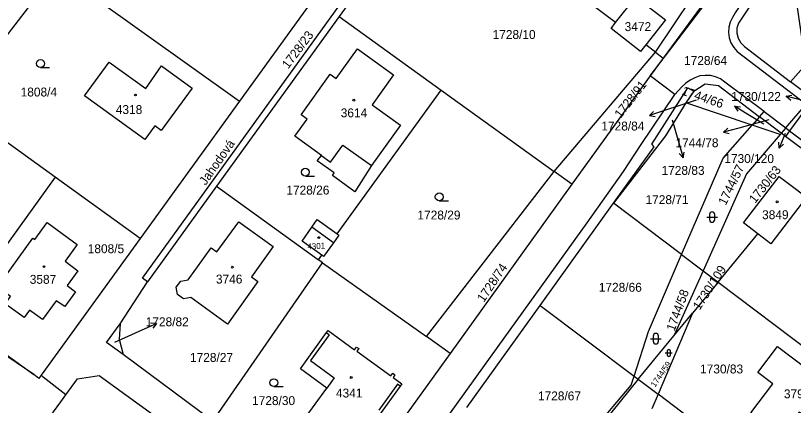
# Model space of a CAD drawing. Extents: x -679220 to -673243, y -1075091 to -1066557.
# Drawn here: x -677162.5 to -677014, y -1072302.1 to -1072227.6 of the extents above; entities that cross this region are included whole.
import ezdxf

# ---------------------------------------------------------------- set-up
doc = ezdxf.new("R2010")
doc.units = 0
for name, color, linetype in [('Hranice parcel', 7, 'Continuous'), ('Parcelní čísla', 7, 'Continuous'), ('Pop  PČ popisy', 7, 'Continuous'), ('Vnitřní kresba', 7, 'Continuous'), ('Značky budov', 7, 'Continuous'), ('Značky kultur', 7, 'Continuous')]:
    doc.layers.add(name, color=color, linetype=linetype)

msp = doc.modelspace()

# ---------------------------------------------------------------- linework, layer by layer
at = {"layer": 'Hranice parcel'}
for p, q in [((-677097.67, -1072213.39), (-677119.75, -1072243.96)), ((-677040.31, -1072234.56), (-677027.35, -1072215.28)), ((-677174.28, -1072244.49), (-677154.6, -1072218.99)), ((-677154.6, -1072218.99), (-677119.75, -1072243.96)), ((-677047.9, -1072228.9), (-677062.31, -1072218.1)), ((-677100.67, -1072227.78), (-677124.1, -1072260.21)), ((-677100.67, -1072227.78), (-677081.22, -1072241.84)), ((-677040.31, -1072234.56), (-677042.16, -1072233.17)), ((-677059.66, -1072257.41), (-677040.31, -1072234.56)), ((-677038.82, -1072235.71), (-677041.29, -1072239.09)), ((-677040.31, -1072234.56), (-677038.82, -1072235.71)), ((-677041.29, -1072239.09), (-677056.26, -1072259.8)), ((-677010.47, -1072243.28), (-677014.49, -1072240.22)), ((-677028.28, -1072240.94), (-677020.41, -1072246.91)), ((-677101.06, -1072269.31), (-677081.22, -1072241.84)), ((-677081.22, -1072241.84), (-677059.66, -1072257.41)), ((-677032.98, -1072242.04), (-677034.52, -1072244.26)), ((-677154.92, -1072258.47), (-677174.28, -1072244.49)), ((-677119.75, -1072243.96), (-677138.7, -1072270.17)), ((-677021.83, -1072248.52), (-677034.52, -1072244.26)), ((-677015.41, -1072249.05), (-677011.5, -1072244.49)), ((-677020.41, -1072246.91), (-677019.54, -1072245.93)), ((-677019.54, -1072245.93), (-677015.41, -1072249.05)), ((-677011.13, -1072244.77), (-677014.68, -1072249.6)), ((-677020.41, -1072246.91), (-677021.83, -1072248.52)), ((-677016.27, -1072250.05), (-677020.41, -1072246.91)), ((-677016.49, -1072250.31), (-677021.83, -1072248.52)), ((-677015.41, -1072249.05), (-677016.27, -1072250.05)), ((-677015.41, -1072249.05), (-677014.68, -1072249.6)), ((-677016.27, -1072250.05), (-677016.49, -1072250.31)), ((-677015.46, -1072250.66), (-677016.27, -1072250.05)), ((-677014.68, -1072249.6), (-677015.46, -1072250.66)), ((-677009.25, -1072255.35), (-677015.46, -1072250.66)), ((-677084.04, -1072288.92), (-677059.66, -1072257.41)), ((-677056.26, -1072259.8), (-677059.66, -1072257.41)), ((-677138.7, -1072270.17), (-677154.92, -1072258.47)), ((-677124.1, -1072260.21), (-677137.29, -1072278.46)), ((-677124.1, -1072260.21), (-677104.64, -1072274.26)), ((-677056.26, -1072259.8), (-677079.53, -1072292.18)), ((-677062.3, -1072282.96), (-677048.3, -1072263.46)), ((-677035.31, -1072273.26), (-677048.3, -1072263.46)), ((-677104.88, -1072266.54), (-677101.06, -1072269.31)), ((-677101.06, -1072269.31), (-677100.73, -1072269.55)), ((-677028.33, -1072278.52), (-677020.74, -1072269.31)), ((-677138.7, -1072270.17), (-677157.58, -1072296.32)), ((-677104.02, -1072273.4), (-677107.79, -1072270.69)), ((-677159.03, -1072296.2), (-677193.06, -1072273.1)), ((-677104.64, -1072274.26), (-677104.02, -1072273.4)), ((-677103.85, -1072274.86), (-677104.64, -1072274.26)), ((-677103.68, -1072273.65), (-677104.02, -1072273.4)), ((-677035.31, -1072273.26), (-677031.21, -1072276.35)), ((-677124.82, -1072305.07), (-677103.85, -1072274.86)), ((-677103.85, -1072274.86), (-677084.04, -1072288.92)), ((-677031.21, -1072276.35), (-677036.76, -1072288.76)), ((-677031.21, -1072276.35), (-677028.33, -1072278.52)), ((-677142.52, -1072286.49), (-677137.29, -1072278.46)), ((-677028.33, -1072278.52), (-677033.21, -1072284.45)), ((-677028.33, -1072278.52), (-676999.23, -1072300.52)), ((-677076.29, -1072302.46), (-677062.3, -1072282.96)), ((-677062.3, -1072282.96), (-677044.39, -1072296.48)), ((-677033.21, -1072284.45), (-677039.8, -1072299.95)), ((-677036.76, -1072288.76), (-677033.21, -1072284.45)), ((-677079.53, -1072292.18), (-677084.04, -1072288.92)), ((-677043.6, -1072297.08), (-677036.76, -1072288.76)), ((-677124.82, -1072305.07), (-677141.95, -1072292.37)), ((-677044.39, -1072296.48), (-677043.6, -1072297.08)), ((-677043.6, -1072297.08), (-677058.73, -1072315.73)), ((-677043.6, -1072297.08), (-677039.8, -1072299.95)), ((-677039.8, -1072299.95), (-677040.98, -1072302.71)), ((-677013.7, -1072319.67), (-677039.8, -1072299.95))]:
    msp.add_line(p, q, dxfattribs=at)
for points in [[(-677137.29, -1072278.46), (-677138.25, -1072277.77), (-677074.28, -1072189.03), (-677070.45, -1072187.06)], [(-677070.45, -1072187.06), (-677078.7, -1072197.36), (-677100.67, -1072227.78)], [(-677041.29, -1072239.09), (-677020.3, -1072211.54), (-677004.4, -1072187.4)], [(-677000.68, -1072190.31), (-677010.81, -1072205.46), (-677025.05, -1072227.04), (-677025.58, -1072227.92), (-677026.06, -1072228.81), (-677026.31, -1072229.79), (-677026.34, -1072230.8), (-677026.21, -1072231.82), (-677025.88, -1072232.78), (-677025.36, -1072233.67), (-677024.7, -1072234.47), (-677011.5, -1072244.49)], [(-677000.98, -1072193.99), (-677009.55, -1072206.46), (-677019.04, -1072220.85), (-677024.42, -1072229.04), (-677024.78, -1072230), (-677024.76, -1072230.97), (-677024.5, -1072231.92), (-677024.01, -1072232.8), (-677023.32, -1072233.51), (-677014.49, -1072240.22)], [(-677014.49, -1072240.22), (-677011.6, -1072236.95), (-677013.33, -1072225.14), (-676993.8, -1072200.73)], [(-677026.98, -1072214.73), (-677026.28, -1072215.76), (-677026.13, -1072216.83), (-677026.28, -1072217.83), (-677026.67, -1072218.76), (-677027.15, -1072219.65), (-677027.69, -1072220.49), (-677038.82, -1072235.71)], [(-677047.9, -1072228.9), (-677044.06, -1072224.02), (-677038.38, -1072228.38), (-677042.16, -1072233.17)], [(-677042.16, -1072233.17), (-677043.16, -1072234.45), (-677048.78, -1072230.02), (-677047.9, -1072228.9)], [(-677104.87, -1072255.34), (-677104.07, -1072254.32), (-677109.18, -1072250.61), (-677106.84, -1072247.36), (-677107.98, -1072246.53), (-677102.4, -1072238.8), (-677101.25, -1072239.61), (-677097.17, -1072233.94), (-677090.3, -1072238.92), (-677094.4, -1072244.63), (-677088.97, -1072248.54), (-677094.54, -1072256.24), (-677097.69, -1072261.24)], [(-677128.79, -1072241.43), (-677134.68, -1072249.56), (-677135.9, -1072248.66), (-677137.8, -1072251.25), (-677149.34, -1072242.93), (-677144.6, -1072236.47), (-677137.62, -1072241.49), (-677134.63, -1072237.21), (-677128.79, -1072241.43)], [(-677019.54, -1072245.93), (-677027.03, -1072240.29), (-677027.88, -1072239.66), (-677028.81, -1072239.26), (-677029.8, -1072239.05), (-677030.81, -1072239.03), (-677031.83, -1072239.12), (-677032.79, -1072239.47), (-677033.69, -1072239.9), (-677034.52, -1072240.49), (-677035.28, -1072241.18), (-677036.59, -1072242.68), (-677041.29, -1072239.09)], [(-677041.02, -1072252.17), (-677034.12, -1072241.4), (-677032.98, -1072242.04)], [(-677032.98, -1072242.04), (-677030.79, -1072240.62), (-677028.28, -1072240.94)], [(-677034.52, -1072244.26), (-677038.39, -1072250.57), (-677048.3, -1072263.46)], [(-677035.31, -1072273.26), (-677027.4, -1072254.81), (-677021.83, -1072248.52)], [(-677016.49, -1072250.31), (-677022.92, -1072257.8), (-677031.21, -1072276.35)], [(-677014.68, -1072249.6), (-677006.87, -1072255.49), (-676981.13, -1072274.94), (-676959.99, -1072291), (-676958.83, -1072291.96), (-676958.3, -1072292.81), (-676957.95, -1072293.75), (-676957.87, -1072294.17)], [(-677048.3, -1072263.46), (-677040.57, -1072252.69), (-677041.02, -1072252.17)], [(-677097.69, -1072261.24), (-677101.99, -1072258.12), (-677101.64, -1072257.62), (-677104.87, -1072255.34)], [(-677154.92, -1072258.47), (-677174.23, -1072285.22), (-677159.03, -1072296.2)], [(-677020.74, -1072269.31), (-677023.47, -1072267.21), (-677016.66, -1072258.36), (-677013.62, -1072260.65)], [(-677013.62, -1072260.65), (-677011.49, -1072262.26), (-677018.3, -1072271.19), (-677020.74, -1072269.31)], [(-677117.45, -1072277.49), (-677116.2, -1072278.39), (-677122.04, -1072286.53), (-677129.02, -1072281.48), (-677130.4, -1072281.69), (-677131.58, -1072280.87), (-677131.8, -1072279.48), (-677130.95, -1072278.33), (-677129.56, -1072278.09), (-677125.13, -1072271.96), (-677124.04, -1072272.73), (-677119.85, -1072266.97), (-677113.32, -1072271.71), (-677117.45, -1072277.49)], [(-677107.79, -1072270.69), (-677105.92, -1072268.04), (-677104.88, -1072266.54)], [(-677165.96, -1072279.43), (-677159.18, -1072270.13), (-677158.81, -1072270.39), (-677156.45, -1072267.15), (-677150.76, -1072271.3), (-677153.05, -1072274.53), (-677150.59, -1072276.39), (-677152.66, -1072279.19), (-677151.05, -1072280.37), (-677153.1, -1072283.2), (-677154.73, -1072282.09), (-677157.33, -1072285.68), (-677159.83, -1072283.85), (-677160.87, -1072285.28), (-677164.47, -1072282.66), (-677163.44, -1072281.26), (-677165.96, -1072279.43)], [(-677100.73, -1072269.55), (-677101.78, -1072271.04), (-677103.68, -1072273.65)], [(-677044.39, -1072296.48), (-677041.62, -1072287.97), (-677035.31, -1072273.26)], [(-677141.95, -1072292.37), (-677145.11, -1072290.03), (-677142.52, -1072286.49)], [(-677142.52, -1072286.49), (-677142.74, -1072289.43), (-677141.95, -1072292.37)], [(-677097.37, -1072290.93), (-677096.97, -1072291.23), (-677097.3, -1072291.73), (-677090.82, -1072296.45), (-677090.46, -1072295.95), (-677090.06, -1072296.24), (-677090.39, -1072296.74), (-677088.75, -1072297.97), (-677089.04, -1072298.39), (-677094.04, -1072305.28), (-677095.71, -1072304.08), (-677100.19, -1072310.23), (-677100.57, -1072309.94), (-677100.25, -1072309.42), (-677106.73, -1072304.71), (-677107.1, -1072305.22), (-677107.49, -1072304.92), (-677103.08, -1072298.76), (-677108.11, -1072295.09), (-677103.11, -1072288.18), (-677102.82, -1072287.76), (-677097.74, -1072291.44), (-677097.37, -1072290.93)], [(-677079.53, -1072292.18), (-677099.85, -1072320.45), (-677104.18, -1072320.27), (-677106.75, -1072318.42)], [(-677020.75, -1072295.82), (-677016.97, -1072290.85), (-677005.82, -1072299.3), (-677008.29, -1072302.54), (-677010.24, -1072301.07), (-677012.31, -1072303.76), (-677012.83, -1072303.35), (-677016.29, -1072307.91), (-677022.1, -1072303.49), (-677017.91, -1072297.98), (-677020.75, -1072295.82)], [(-677157.58, -1072296.32), (-677158.02, -1072296.93), (-677159.03, -1072296.2)], [(-677152.92, -1072300.07), (-677157.19, -1072296.71), (-677157.58, -1072296.32)], [(-677152.92, -1072300.07), (-677150.69, -1072297.02), (-677146.5, -1072296.35), (-677128.69, -1072309.31)], [(-677059.34, -1072315.27), (-677044.95, -1072298.19), (-677044.39, -1072296.48)], [(-677169.31, -1072322.45), (-677153.83, -1072301.4), (-677152.92, -1072300.07)]]:
    msp.add_lwpolyline(points, dxfattribs=at)
at = {"layer": 'Pop  PČ popisy'}
for p, q in [((-677015.33, -1072243.01), (-677014.24, -1072242.77)), ((-677012.42, -1072243.74), (-677015.33, -1072243.01)), ((-677015.33, -1072243.01), (-677014.48, -1072243.74)), ((-677032.54, -1072243.76), (-677038.59, -1072245.75)), ((-677038.59, -1072245.75), (-677041.44, -1072246.68)), ((-677041.44, -1072246.68), (-677040.65, -1072245.89)), ((-677022.63, -1072246.48), (-677025.18, -1072244.89)), ((-677025.18, -1072244.89), (-677024.06, -1072245)), ((-677025.18, -1072244.89), (-677024.59, -1072245.84)), ((-677041.44, -1072246.68), (-677040.34, -1072246.84)), ((-677037.14, -1072247.53), (-677035.85, -1072251.88)), ((-677018.62, -1072247.5), (-677024.4, -1072249.09)), ((-677019.63, -1072248.32), (-677022.63, -1072246.48)), ((-677024.4, -1072249.09), (-677027.3, -1072249.87)), ((-677027.3, -1072249.87), (-677026.46, -1072249.12)), ((-677027.3, -1072249.87), (-677026.2, -1072250.09)), ((-677015.55, -1072250.12), (-677016.67, -1072252.9)), ((-677035.85, -1072251.88), (-677035.02, -1072254.77)), ((-677016.67, -1072252.9), (-677016.76, -1072251.79)), ((-677016.67, -1072252.9), (-677015.83, -1072252.16)), ((-677035.02, -1072254.77), (-677035.78, -1072253.94)), ((-677035.02, -1072254.77), (-677034.82, -1072253.66)), ((-677143.55, -1072290), (-677138.34, -1072287.65)), ((-677138.34, -1072287.65), (-677135.6, -1072286.43)), ((-677135.6, -1072286.43), (-677136.72, -1072286.38)), ((-677135.6, -1072286.43), (-677136.31, -1072287.29))]:
    msp.add_line(p, q, dxfattribs=at)
at = {"layer": 'Vnitřní kresba'}
for p, q in [((-677102.33, -1072255.58), (-677099.97, -1072252.32)), ((-677099.97, -1072252.32), (-677094.54, -1072256.24)), ((-677104.07, -1072254.32), (-677102.33, -1072255.58)), ((-677101.78, -1072271.04), (-677105.92, -1072268.04)), ((-677102.61, -1072288.57), (-677106.18, -1072293.5)), ((-677103.11, -1072288.18), (-677102.61, -1072288.57)), ((-677106.18, -1072293.5), (-677101.65, -1072296.81)), ((-677101.65, -1072296.81), (-677103.08, -1072298.76)), ((-677089.54, -1072298.04), (-677093.14, -1072302.98)), ((-677089.04, -1072298.39), (-677089.54, -1072298.04))]:
    msp.add_line(p, q, dxfattribs=at)
msp.add_lwpolyline([(-677107.61, -1072342.81), (-677072.92, -1072294.47), (-677053.37, -1072267.19), (-677046.38, -1072257.41), (-677043.02, -1072252.23), (-677036.59, -1072242.68)], dxfattribs=at)
at = {"layer": 'Značky budov'}
for centre in [(-677139.61, -1072242.76), (-677097.9, -1072243.76), (-677017.06, -1072263.16), (-677104.59, -1072270.01), (-677157.06, -1072275.56), (-677121.1, -1072275.67), (-677098.39, -1072296.75)]:
    msp.add_circle(centre, 0.175, dxfattribs=at)
at = {"layer": 'Značky kultur'}
for p, q in [((-677157.73, -1072237.5), (-677155.98, -1072237.5)), ((-677107.15, -1072258.26), (-677105.4, -1072258.26)), ((-677081.59, -1072262.97), (-677079.84, -1072262.97)), ((-677030.48, -1072266.08), (-677028.48, -1072266.08)), ((-677029.98, -1072265.58), (-677029.98, -1072266.58)), ((-677028.98, -1072266.58), (-677028.98, -1072265.58)), ((-677040.73, -1072288.83), (-677040.73, -1072289.83)), ((-677039.73, -1072289.83), (-677039.73, -1072288.83)), ((-677041.23, -1072289.33), (-677039.23, -1072289.33)), ((-677038.43, -1072292.06), (-677037.09, -1072292.06)), ((-677038.09, -1072291.73), (-677038.09, -1072292.4)), ((-677037.43, -1072292.4), (-677037.43, -1072291.73)), ((-677113.17, -1072298.48), (-677111.42, -1072298.48))]:
    msp.add_line(p, q, dxfattribs=at)
for centre in [(-677157.73, -1072236.75), (-677107.15, -1072257.51), (-677081.59, -1072262.22), (-677113.17, -1072297.73)]:
    msp.add_circle(centre, 0.75, dxfattribs=at)
for centre, radius, start, end in [((-677029.48, -1072265.58), 0.5, 0, 180), ((-677029.48, -1072266.58), 0.5, 180, 359.9879), ((-677040.23, -1072288.83), 0.5, 0, 180), ((-677040.23, -1072289.83), 0.5, 180, 359.9879), ((-677037.76, -1072291.73), 0.335, 0, 180), ((-677037.76, -1072292.4), 0.335, 180, 359.9879)]:
    msp.add_arc(centre, radius, start, end, dxfattribs=at)

# ---------------------------------------------------------------- texts
at = {"layer": 'Parcelní čísla'}
for s, p in [('3472', (-677046.19, -1072230.54)), ('1728/10', (-677071.4, -1072232.05)), ('1728/64', (-677034.84, -1072237.02)), ('1808/4', (-677161.52, -1072243.04)), ('1730/122', (-677025.83, -1072243.89)), ('4318', (-677143.35, -1072246.39)), ('3614', (-677100.4, -1072247.02)), ('1728/84', (-677050.63, -1072249.54)), ('1744/78', (-677036.48, -1072252.74)), ('1730/120', (-677027.15, -1072255.76)), ('1728/83', (-677039.14, -1072258.02)), ('1728/26', (-677110.78, -1072261.78)), ('1728/71', (-677042.2, -1072263.61)), ('1728/29', (-677085.75, -1072266.55)), ('3849', (-677019.94, -1072266.49)), ('1808/5', (-677148.71, -1072272.99)), ('3587', (-677159.78, -1072278.84)), ('3746', (-677124.23, -1072278.79)), ('1728/66', (-677051.12, -1072280.36)), ('1728/82', (-677137.64, -1072286.95)), ('1728/27', (-677129.18, -1072293.76)), ('1730/83', (-677031.78, -1072295.97)), ('4341', (-677101.31, -1072300.57)), ('1728/67', (-677062.74, -1072301.12)), ('3798', (-677015.77, -1072300.72)), ('1728/30', (-677117.33, -1072302.02))]:
    msp.add_text(s, height=1.7, dxfattribs=at).set_placement(p)
for s, height, rotation, p in [('1728/23', 1.7, 53, (-677110.43, -1072237.87)), ('1728/91', 1.7, 52, (-677046.95, -1072247.31)), ('1744/66', 1.7, 341, (-677035.44, -1072242.64)), ('1744/57', 1.7, 64, (-677026.88, -1072263.97)), ('1730/63', 1.7, 52, (-677021.27, -1072263.59)), ('4301', 1.139, 3, (-677106.74, -1072272.29)), ('1728/74', 1.7, 56, (-677073.08, -1072282.51)), ('1730/109', 1.7, 57, (-677031.87, -1072283.99)), ('1744/58', 1.7, 70, (-677036.68, -1072288.02)), ('1744/59', 1.14, 55, (-677040.38, -1072298.7))]:
    msp.add_text(s, height=height, rotation=rotation, dxfattribs=at).set_placement(p)
at = {"layer": 'Pop  PČ popisy'}
msp.add_text('Jahodová', height=1.7, rotation=55, dxfattribs=at).set_placement((-677126.18, -1072260.13))

doc.saveas('drawing.dxf')
